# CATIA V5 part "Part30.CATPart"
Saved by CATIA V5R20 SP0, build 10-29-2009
Part number: socket countersunk head screw_din_DIN 7991 - M8 x 20 --- 20N
Revision: ANY
Definition: UNKNOWN
Nomenclature: socket countersunk head screw_din_DIN 7991 - M8 x 20 --- 20N
Source: Unknown
Bounding box of the stored display mesh (mm): x 0 to 20, y -7.59 to 7.59, z -7.785 to 7.785
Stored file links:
  C:\Users\Utente\Desktop\IO LAVORO\3D X SITO CF\CUMSA\3D files GR\GR 424546-10\Part30.CATPart
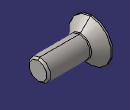
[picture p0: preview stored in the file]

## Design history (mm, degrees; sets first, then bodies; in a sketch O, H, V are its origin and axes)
Body1 "Hex" (main body)
  Solid1: solid without history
